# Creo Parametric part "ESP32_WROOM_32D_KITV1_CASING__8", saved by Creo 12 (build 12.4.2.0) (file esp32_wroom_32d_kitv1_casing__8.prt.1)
Units: Custom; MM, KILOGRAM, SECS

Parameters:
  PTC_WM_ITERATION = "0"
  PTC_WM_VERSION = "-.0"
  PTC_WM_LIFECYCLE_STATE = "In Work"
  PTC_WM_LIFECYCLE = "MO_CADDocument"
  PTC_WM_CREATED_BY = "Maximilian Roepper (Z0017RMS: MO)"
  PTC_WM_CREATED_ON = "18-Sep-26 11:36:42 AM"
  PTC_WM_MODIFIED_BY = "Maximilian Roepper (Z0017RMS: MO)"
  PTC_WM_MODIFIED_ON = "18-Sep-26 11:36:46 AM"
  PDMLINKNUMBER = "PDM000071455313"
  PTC_WM_NAME = "esp32_wroom_32d_kitv1_casing__8.prt"
  PTC_WM_NUMBER = "PDM000071455313"

Other parameters: WEIGHT, WEIGHT_FACTOR, WEIGHT_ADD, _MASS_TEMP, _DIFF_TEMP, MC_ERRORS, SUPPLIER

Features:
  1. coordinate system
  2. datum plane "PRT_YZ"
  3. datum plane "PRT_XY"
  4. datum plane "PRT_XZ"
  5. coordinate system
  6. datum axis
  7. datum axis
  8. datum axis
  9. coordinate system
  10. imported feature
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
Other named items: PRT, SIEMENS_MO, DRW_VIEW_ORG, PRT_X, PRT_Y, PRT_Z, CS0, ROUGH_GROB

Layers: 00_STD_CSYS-KSYS, 01_STD_PLANES-EBENEN, 02_STD_AXES-ACHSEN, 03_STD_CSYS-KSYS, 24_IMPORT_FEAT-IMPORT_KE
